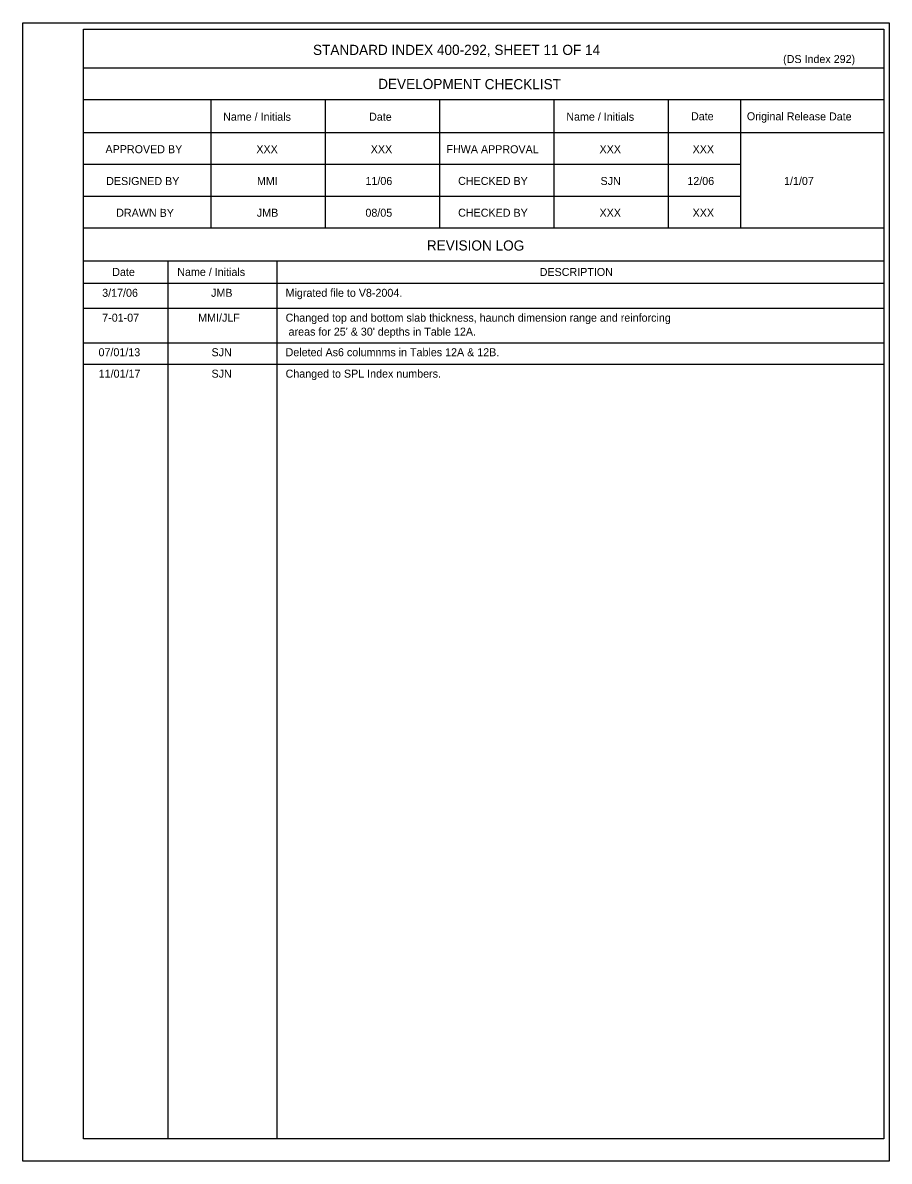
# Model space of a CAD drawing. Extents: x 10342.77 to 10344.98, y 76371.53 to 76372.62.
# Drawn here: x 10344.301 to 10344.983, y 76371.667 to 76372.563 of the extents above; entities that cross this region are included whole.
import ezdxf

# ---------------------------------------------------------------- set-up
doc = ezdxf.new("R2010")
doc.units = 0
for name, color, linetype in [('AdhocPoint_dp', 7, 'Continuous'), ('Border', 7, 'Continuous'), ('PlotBorder_dp', 7, 'Continuous')]:
    doc.layers.add(name, color=color, linetype=linetype)

msp = doc.modelspace()

# ---------------------------------------------------------------- linework, layer by layer
at = {"layer": 'Border'}
for p, q in [((10344.97841, 76372.52706), (10344.34883, 76372.52706)), ((10344.97841, 76372.50206), (10344.34883, 76372.50206)), ((10344.44883, 76372.50206), (10344.44883, 76372.40119)), ((10344.53883, 76372.50206), (10344.53883, 76372.40119)), ((10344.62883, 76372.50206), (10344.62883, 76372.40119)), ((10344.71883, 76372.50206), (10344.71883, 76372.40119)), ((10344.80883, 76372.50206), (10344.80883, 76372.40119)), ((10344.86554, 76372.50206), (10344.86554, 76372.40119)), ((10344.97841, 76372.47619), (10344.34883, 76372.47619)), ((10344.86554, 76372.45119), (10344.34883, 76372.45119)), ((10344.86554, 76372.42619), (10344.34883, 76372.42619)), ((10344.97841, 76372.40119), (10344.34883, 76372.40119)), ((10344.97841, 76372.37532), (10344.34883, 76372.37532)), ((10344.41509, 76372.37532), (10344.41509, 76371.68449)), ((10344.50078, 76372.37532), (10344.50078, 76371.68449)), ((10344.97841, 76372.3577), (10344.34883, 76372.3577)), ((10344.301, 76371.66695), (10344.301, 76371.66695))]:
    msp.add_line(p, q, dxfattribs=at)
for points in [[(10344.301, 76372.56278), (10344.98267, 76372.56278), (10344.98267, 76371.66695), (10344.301, 76371.66695)], [(10344.34884, 76372.5577), (10344.97841, 76372.5577), (10344.97841, 76371.68449), (10344.34884, 76371.68449)]]:
    msp.add_lwpolyline(points, close=True, dxfattribs=at)
at = {"layer": 'PlotBorder_dp'}
for p, q in [((10344.34884, 76372.33813), (10344.97841, 76372.33813)), ((10344.34884, 76372.31094), (10344.97841, 76372.31094)), ((10344.34884, 76372.2941), (10344.97841, 76372.2941))]:
    msp.add_line(p, q, dxfattribs=at)

# ---------------------------------------------------------------- texts
at = {"layer": 'AdhocPoint_dp'}
for s, height, p in [('STANDARD INDEX 400-292, SHEET 11 OF 14', 0.008, (10344.52933, 76372.53745)), ('(DS Index 292)', 0.0063, (10344.89918, 76372.5311)), ('XXX', 0.0063, (10344.48477, 76372.46015)), ('XXX', 0.0063, (10344.57477, 76372.46015)), ('XXX', 0.0063, (10344.75476, 76372.46015)), ('XXX', 0.0063, (10344.82799, 76372.46015)), ('MMI', 0.0063, (10344.48526, 76372.43515)), ('11/06', 0.0063, (10344.57062, 76372.43515)), ('SJN', 0.0063, (10344.75553, 76372.43515)), ('12/06', 0.0063, (10344.82385, 76372.43515)), ('1/1/07', 0.0063, (10344.89992, 76372.43515)), ('JMB', 0.0063, (10344.48517, 76372.41015)), ('08/05', 0.0063, (10344.57058, 76372.41015)), ('XXX', 0.0063, (10344.75476, 76372.41015)), ('XXX', 0.0063, (10344.82799, 76372.41015)), ('DESCRIPTION', 0.0063, (10344.70769, 76372.36354)), ('3/17/06', 0.0063, (10344.36349, 76372.34714)), ('JMB', 0.0063, (10344.44913, 76372.34714)), ('Migrated file to V8-2004.', 0.0063, (10344.50777, 76372.34714)), ('7-01-07', 0.0063, (10344.36351, 76372.32757)), ('MMI/JLF', 0.0063, (10344.439, 76372.32757)), ('Changed top and bottom slab thickness, haunch dimension range and reinforcing ', 0.0063, (10344.50778, 76372.32757)), (" areas for 25' & 30' depths in Table 12A.", 0.0063, (10344.50778, 76372.31658)), ('07/01/13', 0.0063, (10344.3606, 76372.30038)), ('SJN', 0.0063, (10344.4495, 76372.30038)), ('Deleted As6 columnms in Tables 12A & 12B.', 0.0063, (10344.50778, 76372.30038)), ('11/01/17', 0.0063, (10344.36075, 76372.28353)), ('SJN', 0.0063, (10344.4495, 76372.28353)), ('Changed to SPL Index numbers.', 0.0063, (10344.50778, 76372.28353))]:
    msp.add_text(s, height=height, dxfattribs=at).set_placement(p)
for s, height, p in [('DEVELOPMENT CHECKLIST', 0.008, (10344.58057, 76372.51071)), ('Name / Initials', 0.0063, (10344.4586, 76372.48578)), ('Date', 0.0063, (10344.57343, 76372.48573)), ('Name / Initials', 0.0063, (10344.7286, 76372.48578)), ('Date', 0.0063, (10344.82671, 76372.48609)), ('Original Release Date', 0.0063, (10344.87066, 76372.48608)), ('APPROVED BY', 0.0063, (10344.36607, 76372.46021)), ('FHWA APPROVAL', 0.0063, (10344.6343, 76372.46021)), ('DESIGNED BY', 0.0063, (10344.3666, 76372.43515)), ('CHECKED BY', 0.0063, (10344.64351, 76372.43521)), ('DRAWN BY', 0.0063, (10344.3745, 76372.41015)), ('CHECKED BY', 0.0063, (10344.64351, 76372.41021)), ('REVISION LOG', 0.008, (10344.61886, 76372.38365)), ('Date', 0.0063, (10344.3714, 76372.36356)), ('Name / Initials', 0.0063, (10344.42254, 76372.36361))]:
    msp.add_text(s, height=height, rotation=359.87563, dxfattribs=at).set_placement(p)

doc.saveas('drawing.dxf')
